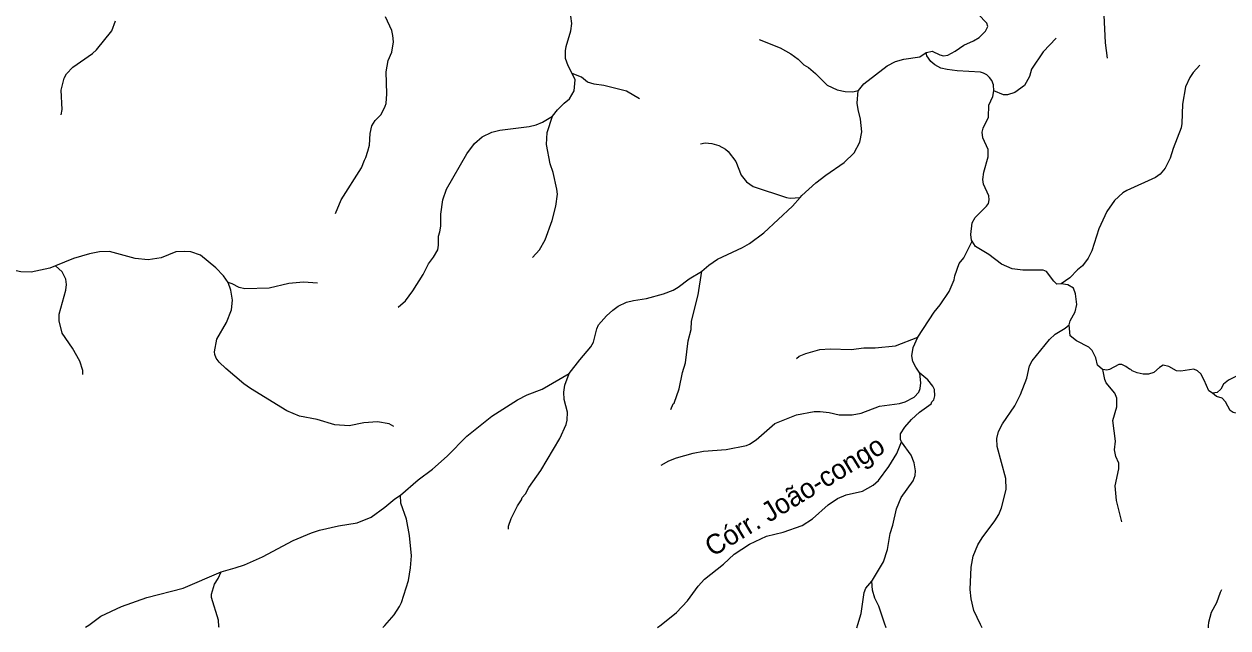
# Model space of a CAD drawing. Extents: x 500 to 555.2, y 9115.7 to 9171.
# Drawn here: x 518.44 to 528.19, y 9115.69 to 9120.58 of the extents above; entities that cross this region are included whole.
import ezdxf
from ezdxf.enums import TextEntityAlignment as Align

# ---------------------------------------------------------------- set-up
doc = ezdxf.new("R2010")
doc.units = 0
doc.header["$LTSCALE"] = 0.064
doc.layers.add('61', color=7, linetype='Continuous')
doc.layers.add('7', color=7, linetype='Continuous', lineweight=25)

msp = doc.modelspace()

# ---------------------------------------------------------------- linework, layer by layer
at = {"layer": '7'}
for points in [[(522.8791, 9120.1811), (522.8471, 9120.2428), (522.8259, 9120.3026), (522.8244, 9120.3635), (522.8295, 9120.3978), (522.867, 9120.5242), (522.8767, 9120.584), (522.8681, 9120.6449), (522.8266, 9120.8153), (522.8162, 9121.0082), (522.8017, 9121.0739), (522.7914, 9121.1679), (522.7394, 9121.343), (522.7289, 9121.406), (522.7243, 9121.5636), (522.7308, 9121.597), (522.7325, 9121.6593), (522.7211, 9121.7473), (522.7045, 9121.8069), (522.6445, 9121.9262), (522.5852, 9121.9916), (522.5251, 9122.0364), (522.4727, 9122.0596), (522.4029, 9122.0785)], [(527.215, 9120.3044), (527.1986, 9120.4291), (527.1875, 9120.6522), (527.1727, 9120.7992), (527.1256, 9120.9455), (527.1186, 9120.9993), (527.0991, 9121.078), (527.0755, 9121.125), (526.9985, 9121.2003), (526.9815, 9121.2237), (526.9299, 9121.3411), (526.9057, 9121.3717), (526.842, 9121.408), (526.785, 9121.4166), (526.7063, 9121.4198), (526.6178, 9121.4047), (526.561, 9121.3738), (526.5371, 9121.3534), (526.4641, 9121.2444), (526.3921, 9121.1641), (526.3608, 9121.1433), (526.3009, 9121.13)], [(525.7474, 9120.3492), (525.75, 9120.3509), (525.7951, 9120.3596), (525.8564, 9120.33), (525.8858, 9120.3241), (525.9222, 9120.3291), (525.9807, 9120.3611), (526.0519, 9120.4107), (526.1289, 9120.4436), (526.1754, 9120.4702), (526.2282, 9120.5216), (526.2457, 9120.56), (526.2372, 9120.5868), (526.1675, 9120.6597), (526.1541, 9120.6889), (526.1527, 9120.7412), (526.1899, 9120.819), (526.2317, 9120.8643), (526.2837, 9120.9081), (526.3226, 9120.9632), (526.3361, 9121.006), (526.3342, 9121.0439), (526.3009, 9121.13)], [(520.96, 9119.0465), (521.0079, 9119.1579), (521.1721, 9119.4149), (521.1954, 9119.4782), (521.2083, 9119.4992), (521.2227, 9119.5512), (521.2363, 9119.5986), (521.2433, 9119.6948), (521.2556, 9119.7562), (521.2839, 9119.8004), (521.3303, 9119.8474), (521.3647, 9119.9147), (521.371, 9119.9376), (521.3759, 9120.0151), (521.3712, 9120.1935), (521.3891, 9120.2847), (521.4168, 9120.3531), (521.4301, 9120.4351), (521.4268, 9120.4875), (521.4166, 9120.5288), (521.3663, 9120.6401)], [(518.7384, 9119.8454), (518.7466, 9119.8893), (518.7401, 9120.0453), (518.7627, 9120.1425), (518.7808, 9120.176), (518.8326, 9120.2308), (518.9916, 9120.343), (519.0243, 9120.3722), (519.1494, 9120.5265), (519.1799, 9120.6074)], [(524.3924, 9120.454), (524.5624, 9120.3876), (524.651, 9120.3399), (524.7105, 9120.2961), (524.7558, 9120.2494), (524.7919, 9120.2278), (524.8491, 9120.1808), (524.9451, 9120.0855), (525.025, 9120.0472), (525.0895, 9120.034), (525.1522, 9120.0325), (525.1968, 9120.0412)], [(526.7995, 9120.4662), (526.6951, 9120.3548), (526.5988, 9120.214), (526.5824, 9120.1562), (526.5435, 9120.084), (526.4657, 9120.0273), (526.4064, 9120.0062), (526.373, 9120.0062), (526.2955, 9120.0394)], [(525.1968, 9120.0412), (525.1969, 9120.0418), (525.2406, 9120.096), (525.4296, 9120.2429), (525.4977, 9120.277), (525.5646, 9120.2961), (525.6958, 9120.3158), (525.7474, 9120.3492)], [(526.2955, 9120.0394), (526.2908, 9120.0889), (526.2773, 9120.1234), (526.2606, 9120.1485), (526.2379, 9120.1686), (526.2115, 9120.1836), (526.1877, 9120.1921), (525.9977, 9120.2012), (525.9161, 9120.2114), (525.8643, 9120.2239), (525.8157, 9120.2506), (525.7841, 9120.2767), (525.7507, 9120.3234), (525.7474, 9120.3492)], [(527.9626, 9120.247), (527.9097, 9120.1883), (527.8814, 9120.147), (527.8473, 9120.0721), (527.8237, 9119.9316), (527.819, 9119.7756), (527.813, 9119.739), (527.7468, 9119.5728), (527.7235, 9119.4936), (527.683, 9119.4142), (527.6408, 9119.3653), (527.6051, 9119.339), (527.3711, 9119.2329), (527.3386, 9119.2125), (527.2732, 9119.1517), (527.2092, 9119.0632), (527.1465, 9118.9216), (527.0876, 9118.7435), (527.0592, 9118.6833), (527.0123, 9118.6236), (526.9731, 9118.5907), (526.911, 9118.5254), (526.8393, 9118.4756)], [(522.7186, 9119.8336), (522.7608, 9119.8865), (522.8129, 9119.9386), (522.8578, 9119.9757), (522.8958, 9120.0398), (522.9031, 9120.1287), (522.8791, 9120.1811)], [(523.4235, 9119.9757), (523.318, 9120.0369), (523.1349, 9120.0829), (523.0557, 9120.0929), (523.0037, 9120.1108), (522.9534, 9120.1505), (522.8791, 9120.1811)], [(524.7269, 9119.1769), (524.7391, 9119.1909), (524.852, 9119.2941), (524.9326, 9119.3572), (525.0813, 9119.4598), (525.1634, 9119.5385), (525.2094, 9119.625), (525.224, 9119.7074), (525.2157, 9119.8105), (525.1946, 9119.8879), (525.188, 9119.9397), (525.1968, 9120.0412)], [(526.1181, 9118.8235), (526.1139, 9118.8301), (526.1077, 9118.8774), (526.1191, 9118.9702), (526.1427, 9119.0151), (526.2354, 9119.1043), (526.2507, 9119.1284), (526.2572, 9119.1556), (526.254, 9119.1884), (526.2097, 9119.2831), (526.2067, 9119.3208), (526.213, 9119.3813), (526.2482, 9119.5063), (526.2492, 9119.5433), (526.2476, 9119.5656), (526.2048, 9119.6587), (526.2001, 9119.7047), (526.207, 9119.7372), (526.2509, 9119.826), (526.2532, 9119.9243), (526.2867, 9119.9928), (526.2955, 9120.0394)], [(521.4702, 9118.2874), (521.5296, 9118.339), (521.5889, 9118.4209), (521.6714, 9118.5532), (521.7152, 9118.6374), (521.7565, 9118.6921), (521.789, 9118.7522), (521.7957, 9118.7908), (521.7959, 9118.8636), (521.8071, 9118.8965), (521.8139, 9118.9437), (521.814, 9119.0414), (521.8321, 9119.1568), (521.8595, 9119.242), (522.024, 9119.5302), (522.087, 9119.6128), (522.1491, 9119.6672), (522.2268, 9119.7061), (522.2918, 9119.7205), (522.5294, 9119.7498), (522.5865, 9119.7632), (522.6376, 9119.7855), (522.7186, 9119.8336)], [(522.5563, 9118.6896), (522.613, 9118.7521), (522.6588, 9118.832), (522.7176, 9118.989), (522.7473, 9119.1043), (522.7587, 9119.2021), (522.7554, 9119.2443), (522.7241, 9119.3793), (522.7013, 9119.4472), (522.6718, 9119.6045), (522.677, 9119.7014), (522.7186, 9119.8336)], [(523.9194, 9119.6113), (523.9566, 9119.6183), (524.0098, 9119.6123), (524.0671, 9119.5969), (524.12, 9119.5667), (524.1415, 9119.5482), (524.2044, 9119.4663), (524.2471, 9119.3555), (524.2911, 9119.3018), (524.3461, 9119.2647), (524.614, 9119.176), (524.6456, 9119.1712), (524.7269, 9119.1769)], [(523.9279, 9118.5785), (523.9853, 9118.6286), (524.0551, 9118.676), (524.2583, 9118.7717), (524.3153, 9118.8036), (524.4323, 9118.8896), (524.664, 9119.1048), (524.7269, 9119.1769)], [(518.6917, 9118.6214), (518.6483, 9118.6038), (518.495, 9118.5706), (518.4129, 9118.5736), (518.1461, 9118.631), (518.1146, 9118.6465), (518.0806, 9118.6728), (517.9665, 9118.8066)], [(525.6782, 9118.0437), (525.8116, 9118.2481), (525.8589, 9118.3061), (525.9334, 9118.4146), (525.9732, 9118.5085), (525.9794, 9118.542), (526.0143, 9118.6416), (526.0508, 9118.6872), (526.1181, 9118.8235)], [(526.8393, 9118.4756), (526.8059, 9118.4738), (526.7797, 9118.4971), (526.7201, 9118.5755), (526.6953, 9118.5871), (526.5291, 9118.5871), (526.4419, 9118.5969), (526.3564, 9118.6359), (526.2541, 9118.715), (526.1465, 9118.7788), (526.1181, 9118.8235)], [(520.0908, 9118.4885), (520.0529, 9118.5403), (519.9915, 9118.6051), (519.8674, 9118.708), (519.7881, 9118.7347), (519.7371, 9118.7395), (519.669, 9118.7363), (519.5493, 9118.6873), (519.4444, 9118.6707), (519.3394, 9118.6821), (519.1295, 9118.7378), (519.0486, 9118.7346), (518.9694, 9118.7203), (518.8382, 9118.681), (518.6917, 9118.6214)], [(518.9145, 9117.7413), (518.9135, 9117.7736), (518.8894, 9117.85), (518.8312, 9117.9566), (518.7471, 9118.078), (518.7238, 9118.1781), (518.7238, 9118.2317), (518.776, 9118.4257), (518.7825, 9118.4724), (518.7758, 9118.5147), (518.7462, 9118.5727), (518.6917, 9118.6214)], [(522.8542, 9117.7517), (522.9396, 9117.8604), (523.0297, 9117.9676), (523.0507, 9118.0033), (523.0785, 9118.1124), (523.0926, 9118.145), (523.1578, 9118.2185), (523.2086, 9118.2643), (523.2525, 9118.2954), (523.319, 9118.3272), (523.3745, 9118.3427), (523.4815, 9118.3589), (523.6192, 9118.3969), (523.6955, 9118.4247), (523.7386, 9118.4496), (523.826, 9118.5162), (523.9262, 9118.577), (523.9279, 9118.5785)], [(523.6779, 9117.4603), (523.6973, 9117.5044), (523.7049, 9117.5112), (523.7449, 9117.6254), (523.7727, 9117.7593), (523.7954, 9117.8375), (523.8185, 9118.0152), (523.8413, 9118.107), (523.8466, 9118.174), (523.8984, 9118.3874), (523.9279, 9118.5785)], [(521.4351, 9117.3206), (521.3956, 9117.3419), (521.3005, 9117.3601), (521.1908, 9117.3505), (521.072, 9117.3257), (520.9555, 9117.334), (520.8118, 9117.3781), (520.6701, 9117.4063), (520.5672, 9117.4488), (520.2715, 9117.6278), (520.2175, 9117.6659), (520.0717, 9117.7905), (520.0189, 9117.8429), (519.9943, 9117.8755), (519.9835, 9117.9032), (519.9818, 9117.926), (520.001, 9118.0296), (520.0771, 9118.1628), (520.1194, 9118.2673), (520.126, 9118.3453), (520.1129, 9118.4247), (520.0908, 9118.4885)], [(520.8142, 9118.4816), (520.7007, 9118.4902), (520.5841, 9118.4801), (520.4226, 9118.4425), (520.2277, 9118.4362), (520.1814, 9118.4467), (520.1243, 9118.4771), (520.0908, 9118.4885)], [(526.9055, 9118.1442), (526.9141, 9118.1781), (526.9529, 9118.2508), (526.9659, 9118.3092), (526.9565, 9118.397), (526.9393, 9118.4429), (526.8954, 9118.4678), (526.8393, 9118.4756)], [(526.199, 9115.6915), (526.1865, 9115.7182), (526.133, 9115.8325), (526.1101, 9115.9266), (526.1032, 9116.0008), (526.1098, 9116.1834), (526.1262, 9116.272), (526.1663, 9116.3626), (526.2004, 9116.4208), (526.3037, 9116.5569), (526.3343, 9116.6077), (526.3575, 9116.6631), (526.3947, 9116.8114), (526.3906, 9116.9011), (526.3214, 9117.159), (526.3198, 9117.224), (526.3322, 9117.2805), (526.3644, 9117.3427), (526.465, 9117.4884), (526.5114, 9117.5809), (526.5607, 9117.7122), (526.5842, 9117.8118), (526.604, 9117.8542), (526.745, 9118.0264), (526.7923, 9118.0703), (526.8736, 9118.1176), (526.9055, 9118.1442)], [(527.1771, 9117.783), (527.1763, 9117.7831), (527.135, 9117.8185), (527.1216, 9117.8774), (527.0919, 9117.9363), (527.0644, 9117.9636), (526.9645, 9118.0163), (526.9135, 9118.0562), (526.9055, 9118.1442)], [(524.6952, 9117.8708), (524.7171, 9117.8907), (524.7719, 9117.9131), (524.885, 9117.9438), (524.9697, 9117.949), (525.1394, 9117.9442), (525.2411, 9117.9588), (525.3336, 9117.9589), (525.4978, 9117.975), (525.6782, 9118.0437)], [(525.6952, 9117.7533), (525.6617, 9117.8026), (525.639, 9117.8479), (525.6294, 9117.8926), (525.6406, 9117.9615), (525.6782, 9118.0437)], [(528.5512, 9118.0022), (528.5098, 9117.9641), (528.4615, 9117.8829), (528.3974, 9117.8158), (528.3026, 9117.7499), (528.1958, 9117.6976), (528.1562, 9117.6642), (528.1349, 9117.625), (528.1029, 9117.5974), (528.0666, 9117.5916)], [(527.3929, 9117.786), (527.3632, 9117.8086), (527.3329, 9117.8227), (527.3079, 9117.8242), (527.2328, 9117.7833), (527.2088, 9117.7786), (527.1771, 9117.783)], [(528.0666, 9117.5916), (528.036, 9117.609), (527.9988, 9117.6977), (527.9711, 9117.7476), (527.9446, 9117.7711), (527.9141, 9117.7864), (527.8099, 9117.7686), (527.7745, 9117.7712), (527.7118, 9117.8081), (527.6671, 9117.8193), (527.6358, 9117.7992), (527.5915, 9117.7594), (527.5481, 9117.7458), (527.5039, 9117.7456), (527.4556, 9117.7554), (527.4158, 9117.7711), (527.4054, 9117.7831), (527.3929, 9117.786)], [(521.4873, 9116.7642), (521.6314, 9116.8889), (521.747, 9116.9763), (521.8659, 9117.0809), (522.0244, 9117.2441), (522.2268, 9117.4051), (522.4368, 9117.5363), (522.515, 9117.5769), (522.6363, 9117.6229), (522.8542, 9117.7517)], [(522.362, 9116.491), (522.3621, 9116.5141), (522.3844, 9116.5776), (522.4353, 9116.6789), (522.4676, 9116.7275), (522.4735, 9116.7463), (522.5003, 9116.7771), (522.5275, 9116.827), (522.6241, 9116.9649), (522.7775, 9117.2237), (522.8289, 9117.3383), (522.839, 9117.3722), (522.8407, 9117.4366), (522.8143, 9117.5402), (522.8113, 9117.5992), (522.8195, 9117.657), (522.8542, 9117.7517)], [(523.6006, 9117.0087), (523.6608, 9117.0443), (523.7225, 9117.0685), (523.8594, 9117.1057), (523.9414, 9117.1206), (524.1257, 9117.1362), (524.2902, 9117.1685), (524.3164, 9117.1787), (524.3704, 9117.2144), (524.5204, 9117.3452), (524.6973, 9117.4146), (524.8402, 9117.4436), (524.8869, 9117.4436), (524.961, 9117.434), (525.0404, 9117.416), (525.1479, 9117.4149), (525.2202, 9117.4304), (525.3685, 9117.4864), (525.5306, 9117.508), (525.5771, 9117.5204), (525.6494, 9117.5594), (525.6865, 9117.5986), (525.6979, 9117.63), (525.703, 9117.6741), (525.6952, 9117.7533)], [(525.5477, 9117.1962), (525.5396, 9117.2173), (525.5389, 9117.2622), (525.5735, 9117.3158), (525.6265, 9117.377), (525.6911, 9117.4381), (525.7877, 9117.5057), (525.7934, 9117.5224), (525.8081, 9117.5379), (525.8159, 9117.5705), (525.8142, 9117.6198), (525.801, 9117.6493), (525.7588, 9117.698), (525.6952, 9117.7533)], [(527.3322, 9116.5491), (527.2896, 9116.7233), (527.2778, 9116.8396), (527.3072, 9116.9785), (527.3073, 9117.0242), (527.2831, 9117.0795), (527.2716, 9117.1321), (527.2793, 9117.2037), (527.2598, 9117.3689), (527.2907, 9117.4815), (527.2908, 9117.5509), (527.2742, 9117.5913), (527.2053, 9117.6756), (527.1944, 9117.7011), (527.1771, 9117.783)], [(529.0429, 9116.8996), (528.962, 9116.9461), (528.9024, 9116.9729), (528.7619, 9117.0543), (528.6003, 9117.1727), (528.5172, 9117.2211), (528.467, 9117.2715), (528.4037, 9117.3901), (528.3685, 9117.4271), (528.3205, 9117.4372), (528.2684, 9117.4274), (528.2328, 9117.4353), (528.2103, 9117.4512), (528.1708, 9117.5213), (528.1449, 9117.5509), (528.0985, 9117.5651), (528.0666, 9117.5916)], [(523.5708, 9115.6929), (523.5989, 9115.7154), (523.7227, 9115.8145), (523.8138, 9115.909), (523.8991, 9116.0275), (523.9502, 9116.0846), (524.1037, 9116.2054), (524.1903, 9116.2882), (524.3164, 9116.3674), (524.4532, 9116.4333), (524.5883, 9116.4657), (524.7424, 9116.5189), (524.8265, 9116.5736), (524.953, 9116.6872), (525.0289, 9116.7384), (525.0994, 9116.7678), (525.2312, 9116.7977), (525.3178, 9116.846), (525.3602, 9116.8854), (525.4431, 9116.9972), (525.5087, 9117.1029), (525.5477, 9117.1962)], [(525.3058, 9116.0702), (525.3125, 9116.0783), (525.4012, 9116.2268), (525.4338, 9116.3245), (525.4553, 9116.4557), (525.4766, 9116.522), (525.5065, 9116.6537), (525.5427, 9116.7456), (525.6419, 9116.8823), (525.6586, 9116.9255), (525.6599, 9116.9627), (525.6495, 9117.0265), (525.6239, 9117.0901), (525.5477, 9117.1962)], [(520.0356, 9116.1439), (520.1485, 9116.1781), (520.2245, 9116.2021), (520.371, 9116.2663), (520.6187, 9116.3975), (520.7659, 9116.4595), (520.8315, 9116.4809), (520.9863, 9116.5172), (521.1357, 9116.5424), (521.2489, 9116.588), (521.3616, 9116.667), (521.4416, 9116.7351), (521.4873, 9116.7642)], [(521.3456, 9115.694), (521.3602, 9115.7105), (521.4366, 9115.7969), (521.4801, 9115.8644), (521.4952, 9115.8972), (521.5529, 9116.0752), (521.5697, 9116.1757), (521.5777, 9116.2733), (521.5613, 9116.4399), (521.5352, 9116.5705), (521.4909, 9116.7017), (521.4873, 9116.7642)], [(518.9369, 9115.6951), (518.962, 9115.7135), (519.0598, 9115.7854), (519.2273, 9115.8641), (519.4324, 9115.9375), (519.7266, 9116.0125), (520.0356, 9116.1439)], [(520.018, 9115.6946), (520.0173, 9115.7025), (520.013, 9115.7543), (519.9557, 9115.9374), (519.9555, 9115.9636), (519.9804, 9116.0435), (520.0109, 9116.0916), (520.0356, 9116.1439)], [(525.1841, 9115.6921), (525.192, 9115.7169), (525.2207, 9115.8075), (525.2438, 9115.9773), (525.2583, 9116.0128), (525.3058, 9116.0702)], [(525.4211, 9115.6919), (525.4094, 9115.728), (525.3641, 9115.8677), (525.3306, 9115.9321), (525.3127, 9115.9971), (525.3058, 9116.0702)], [(528.1395, 9115.998), (528.1271, 9115.976), (528.0997, 9115.8927), (528.054, 9115.8139), (528.0342, 9115.7352), (528.0323, 9115.7068), (528.0312, 9115.6904)]]:
    msp.add_lwpolyline(points, dxfattribs=at)

# ---------------------------------------------------------------- texts
at = {"layer": '61'}
msp.add_text('Córr. João-congo', height=0.16, rotation=31.329, dxfattribs=at).set_placement((524.7218, 9116.6922), align=Align.CENTER)

doc.saveas('drawing.dxf')
